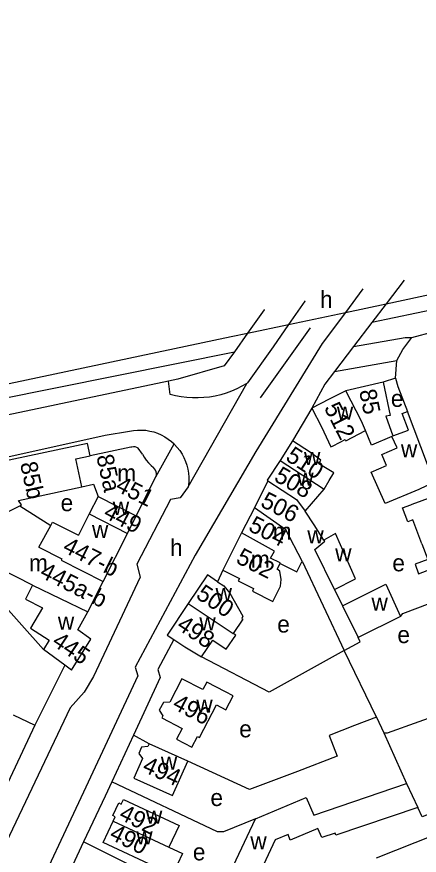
# Model space of a CAD drawing. Extents: x 163026 to 166241, y 382475 to 384501.
# Drawn here: x 163806.9 to 163901.8, y 384015.1 to 384213 of the extents above; entities that cross this region are included whole.
import ezdxf

# ---------------------------------------------------------------- set-up
doc = ezdxf.new("R2010")
doc.units = 0
for name, color, linetype in [('BLT_Basislijn', 7, 'Continuous'), ('BLT_Bebouwing', 7, 'Continuous'), ('BLT_Centroide', 7, 'Continuous'), ('BLT_Huisnummer', 7, 'Continuous'), ('BLT_Huisnummer_ tussenligend', 7, 'Continuous'), ('BLT_Huisnummer_reeks', 7, 'Continuous'), ('BLT_Onderverdeling_panden', 7, 'Continuous'), ('BLT_Spoorlijn', 7, 'Continuous'), ('BLT_Vlakafsluiter', 7, 'Continuous')]:
    doc.layers.add(name, color=color, linetype=linetype)

msp = doc.modelspace()

# ---------------------------------------------------------------- linework, layer by layer
at = {"layer": 'BLT_Basislijn'}
for p, q in [((163969.43, 384157.19), (163890.65, 384140.81)), ((163898.25, 384150.79), (163894.03, 384145.25)), ((163865.29, 384143.83), (163861.35, 384138.3)), ((163894.03, 384145.25), (163890.65, 384140.81)), ((163876.12, 384139.55), (163864.3, 384123.02)), ((163890.65, 384140.81), (163886.32, 384135.12)), ((163861.35, 384138.3), (163858.24, 384133.92)), ((163787.39, 384119.63), (163858.24, 384133.92)), ((163858.24, 384133.92), (163855.85, 384130.55)), ((163886.32, 384135.12), (163881.85, 384129.25)), ((163881.85, 384129.25), (163896.54, 384131.86)), ((163896.24, 384127.64), (163896.54, 384131.86)), ((163855.85, 384130.55), (163844.94, 384127.47)), ((163896.24, 384127.64), (163893.35, 384126.7)), ((163844.94, 384127.47), (163842.68, 384126.99)), ((163843.09, 384123.84), (163842.68, 384126.99)), ((163876.52, 384120.62), (163871.98, 384112.85)), ((163839.75, 384104.35), (163844.03, 384112.15)), ((163813.27, 384063.63), (163795.65, 384083.33)), ((163855.5, 384082.37), (163854.28, 384079.63)), ((163891.8, 384047.64), (163884.13, 384063.39)), ((163818.29, 384059.92), (163811.17, 384045.74)), ((163806.07, 384048.22), (163811.17, 384045.74)), ((163891.8, 384047.64), (163893.52, 384043.92)), ((163811.17, 384045.74), (163788.45, 383997.79)), ((163834.43, 384043.38), (163829.33, 384032.4)), ((163838.14, 384041.35), (163834.43, 384043.38)), ((163893.52, 384043.92), (163898.8, 384032.01)), ((163822.68, 384018.2), (163814.06, 383999.82)), ((163853.46, 384002.93), (163822.68, 384018.2))]:
    msp.add_line(p, q, dxfattribs=at)
for points in [[(163900.11, 384137.3), (163905.37, 384138.71), (164182.17, 384196.48), (164249.9, 384212.98), (164253.88, 384212.82), (164257.32, 384211.62), (164261.05, 384208.36), (164262.81, 384205.4), (164265.99, 384192.34), (164268.94, 384175.29), (164269.89, 384164.18), (164270.1, 384149.11), (164272.14, 384146.86), (164275.23, 384146.44), (164277.11, 384147)], [(163888.54, 384148.75), (163884.42, 384143.2)], [(163874.87, 384145.84), (163871.05, 384140.36)], [(163874.92, 384145.9), (163874.87, 384145.84)], [(163865.33, 384143.89), (163865.29, 384143.83)], [(163884.42, 384143.2), (163878.98, 384135.87), (163863.28, 384110.37), (163849.01, 384085.89)], [(163871.05, 384140.36), (163867.36, 384135.06), (163861.31, 384126.59)], [(163886.32, 384135.12), (163898.52, 384137.28), (163900.11, 384137.3)], [(163896.54, 384131.86), (163898, 384134.42), (163900.11, 384137.3)], [(163881.85, 384129.25), (163879.59, 384126.29), (163876.52, 384120.62)], [(163896.24, 384127.64), (163896.81, 384125.69), (163899.1, 384119.78)], [(163842.68, 384126.99), (163680.68, 384092.81), (163440.33, 384043.29)], [(163861.15, 384126.44), (163860, 384125.76), (163858.8, 384125.15), (163857.57, 384124.61), (163856.31, 384124.15), (163855.03, 384123.76), (163853.72, 384123.46), (163852.4, 384123.22), (163851.07, 384123.07), (163849.73, 384123), (163848.38, 384123.01), (163847.04, 384123.1), (163845.71, 384123.27), (163844.39, 384123.51), (163843.09, 384123.84)], [(163861.31, 384126.59), (163861.25, 384126.51), (163861.15, 384126.44)], [(163779.97, 384103.61), (163827.81, 384114.22), (163833.51, 384115.18)], [(163833.51, 384115.18), (163834.46, 384115.35), (163835.42, 384115.43), (163836.38, 384115.43), (163837.34, 384115.36), (163838.29, 384115.2), (163839.22, 384114.97), (163840.13, 384114.66), (163841.02, 384114.27), (163841.86, 384113.82), (163842.67, 384113.29), (163843.43, 384112.7), (163844.03, 384112.15)], [(163844.03, 384112.15), (163844.14, 384112.05), (163844.79, 384111.34), (163845.38, 384110.58), (163845.9, 384109.77), (163846.36, 384108.92), (163846.74, 384108.04), (163847.05, 384107.13), (163847.29, 384106.2), (163847.44, 384105.25), (163847.52, 384104.29), (163847.51, 384103.33), (163847.43, 384102.37), (163847.37, 384102.01)], [(163847.37, 384102.01), (163845.44, 384099.45), (163843.19, 384099.05), (163835.24, 384083.74), (163836.06, 384080.68), (163825.05, 384057.22), (163822.81, 384053.55), (163819.54, 384049.88), (163804.46, 384018.05)], [(163849.01, 384085.89), (163834.84, 384059.46), (163835.45, 384057.42), (163823.21, 384031.1), (163809.15, 384001.11), (163805.88, 383997.85)], [(163897.43, 384071.44), (163897.96, 384072.12), (163904.4, 384074.58)], [(163844, 384065.97), (163840.22, 384058.92), (163840.78, 384057.04), (163834.43, 384043.38)], [(163884.13, 384063.39), (163866.49, 384053.56), (163850.51, 384061.87)], [(163923.18, 384054.38), (163930.98, 384035.41), (163902.51, 384024.13), (163901.48, 384026.31)], [(163893.52, 384043.92), (163894.32, 384043.98), (163909.33, 384049.29)], [(163891.8, 384047.64), (163886.54, 384045.65), (163880.62, 384043.34), (163882.46, 384038.46), (163873.12, 384034.83), (163861.81, 384030.6), (163847.31, 384037.23)], [(163829.33, 384032.4), (163827.74, 384028.99), (163822.68, 384018.2)], [(163863.25, 384023.62), (163855.66, 384020.56), (163854.29, 384020.61), (163829.33, 384032.4)], [(163891.79, 384014.44), (163932, 384030.42), (163939.47, 384011.72), (163939.8, 384010.54)]]:
    msp.add_lwpolyline(points, dxfattribs=at)
at = {"layer": 'BLT_Bebouwing'}
for p, q in [((163905.38, 384103.11), (163899.1, 384119.78)), ((163871.98, 384112.85), (163869.01, 384108.25)), ((163833.86, 384111.36), (163824.22, 384109.32)), ((163836.6, 384109.72), (163835.58, 384111.14)), ((163835.11, 384095.14), (163839.75, 384104.35)), ((163807.31, 384098.8), (163822.3, 384102.05)), ((163822.3, 384102.05), (163825.01, 384102.63)), ((163825.01, 384102.63), (163826.1, 384099.71)), ((163866.15, 384103.4), (163862.96, 384097.1)), ((163874.91, 384096.29), (163879.44, 384101.5)), ((163826.1, 384099.71), (163824.04, 384095.66)), ((163807.68, 384097.56), (163814.93, 384092.93)), ((163862.96, 384097.1), (163859.96, 384091.18)), ((163824.04, 384095.66), (163821.48, 384090.61)), ((163833.04, 384091.04), (163835.11, 384095.14)), ((163827.3, 384079.68), (163833.04, 384091.04)), ((163859.96, 384091.18), (163855.5, 384082.37)), ((163823.68, 384072.51), (163827.3, 384079.68)), ((163881.85, 384077.8), (163883.76, 384073.93)), ((163819.84, 384058.77), (163824.4, 384066.03)), ((163844, 384065.97), (163846.6, 384064.24)), ((163846.6, 384064.24), (163850.51, 384061.87)), ((163818.29, 384059.92), (163813.27, 384063.63)), ((163819.84, 384058.77), (163818.29, 384059.92)), ((163898.8, 384032.01), (163901.48, 384026.31))]:
    msp.add_line(p, q, dxfattribs=at)
for points in [[(163893.35, 384126.7), (163884.52, 384124.72)], [(163893.35, 384126.7), (163894.97, 384118.89), (163893.97, 384118.68), (163895.6, 384114.04)], [(163884.52, 384124.72), (163880.64, 384122.73), (163876.52, 384120.62)], [(163876.52, 384120.62), (163878.78, 384116.17), (163880.99, 384111.5), (163881.42, 384111.59), (163883.16, 384112.53), (163884.34, 384113.17), (163884.5, 384112.88), (163889.15, 384115.32)], [(163895.6, 384114.04), (163899.3, 384115.43), (163897.84, 384119.3), (163899.1, 384119.78)], [(163895.4, 384113.89), (163890.59, 384111.87), (163889.15, 384115.32)], [(163905.38, 384103.11), (163901.76, 384101.43), (163893.77, 384098.05), (163890.52, 384105.5), (163894.14, 384107.07), (163893.02, 384109.64), (163896.61, 384111.21), (163895.4, 384113.89)], [(163824.22, 384109.32), (163823.61, 384112.25), (163795.05, 384106.22), (163796.06, 384103.37)], [(163879.44, 384101.5), (163880.64, 384103.49), (163881.74, 384105.32), (163878.13, 384107.48), (163878.65, 384108.34), (163876.17, 384110.13), (163871.98, 384112.85)], [(163835.58, 384111.14), (163835.23, 384111.32), (163834.84, 384111.43), (163834.45, 384111.46), (163834.06, 384111.41), (163833.86, 384111.36)], [(163836.6, 384109.72), (163837, 384108.99), (163837.46, 384108.31), (163838, 384107.67), (163838.59, 384107.08), (163839.16, 384106.61)], [(163869.01, 384108.25), (163866.01, 384103.62), (163866.15, 384103.4)], [(163839.75, 384104.35), (163839.85, 384104.75), (163839.86, 384105.16), (163839.8, 384105.57), (163839.66, 384105.95), (163839.44, 384106.3), (163839.17, 384106.61), (163839.16, 384106.61)], [(163807.68, 384097.56), (163808.03, 384097.74), (163807.31, 384098.8)], [(163902.48, 384088.55), (163900.33, 384094.23), (163899.15, 384093.78), (163897.91, 384097.05), (163899.83, 384097.77), (163900.2, 384097.91), (163904.87, 384099.68), (163906.07, 384096.52), (163907.07, 384096.9)], [(163879.38, 384089.45), (163877.03, 384093.05), (163874.91, 384096.29)], [(163810.65, 384078.82), (163798.71, 384084.88), (163804.89, 384089.78), (163802.84, 384092.04)], [(163814.93, 384092.93), (163815.35, 384093.72), (163821.48, 384090.61)], [(163881.85, 384077.8), (163886.84, 384080.3), (163882.11, 384091), (163879.38, 384089.45)], [(163902.48, 384088.55), (163903.87, 384084.89), (163900.85, 384083.74), (163901.7, 384081.5), (163904.7, 384082.69)], [(163869.01, 384083.94), (163872.96, 384081.94), (163874.24, 384084.47)], [(163874.24, 384084.47), (163884.13, 384063.39)], [(163855.5, 384082.37), (163859.42, 384080.39), (163859.14, 384079.83), (163862.78, 384077.99), (163862.49, 384077.41), (163867.33, 384074.96), (163869.15, 384078.57), (163869.27, 384080.16), (163868.93, 384082.14), (163868.33, 384082.61), (163869.01, 384083.94)], [(163854.28, 384079.63), (163851.89, 384081.23), (163847.37, 384074.46)], [(163810.65, 384078.82), (163808.96, 384075.49), (163813, 384073.44), (163810.2, 384068.68), (163814.61, 384065.86), (163813.27, 384063.63)], [(163854.28, 384079.63), (163855.76, 384078.65), (163857.16, 384076.94), (163860.25, 384071.47), (163860, 384070.97), (163860.24, 384070.8), (163857.97, 384067.4)], [(163883.76, 384073.93), (163893.99, 384079.07), (163897.43, 384071.44)], [(163847.37, 384074.46), (163842.41, 384067.03), (163844, 384065.97)], [(163824.4, 384066.03), (163821.36, 384068.23), (163823.68, 384072.51)], [(163897.43, 384071.44), (163887.44, 384066.49)], [(163850.51, 384061.87), (163853.15, 384065.82), (163856.31, 384063.71), (163858.62, 384066.97), (163857.97, 384067.4)], [(163884.13, 384063.39), (163887.95, 384065.46), (163887.44, 384066.49)], [(163856.26, 384049.42), (163857.97, 384052.69), (163856.18, 384053.63), (163851.74, 384055.95), (163850.81, 384054.15), (163845.89, 384056.72), (163843.01, 384051.2), (163841.52, 384051.14), (163840.55, 384049.28), (163841.39, 384047.97), (163841.15, 384047.52), (163845.94, 384045.01), (163844.6, 384042.46), (163848.24, 384040.56), (163849.57, 384043.1), (163850.02, 384042.87), (163854.04, 384050.57), (163856.26, 384049.42)], [(163838.14, 384041.35), (163837.85, 384040.69), (163836.35, 384040.54), (163835.71, 384039.11), (163836.6, 384037.88), (163834.52, 384033.26), (163839.08, 384031.21), (163843.67, 384029.14), (163847.31, 384037.23)], [(163847.31, 384037.23), (163842.71, 384039.3), (163838.14, 384041.35)], [(163875.21, 384028.67), (163876.97, 384024.51), (163898.8, 384032.01)], [(163863.25, 384023.62), (163875.21, 384028.67)], [(163829.69, 384023.13), (163830.14, 384024.14), (163829.58, 384024.41), (163830.97, 384027.42), (163831.56, 384027.14), (163832.07, 384028.23), (163845.2, 384022.08), (163842.83, 384016.99)], [(163901.48, 384026.31), (163882.18, 384019.8), (163881.99, 384020.3), (163878.85, 384019.21), (163877.95, 384021.4), (163871.44, 384018.65), (163870.9, 384019.94), (163867.9, 384018.68), (163862.99, 384008.21), (163862.34, 384005.84), (163863.43, 384003.15)], [(163842.83, 384016.99), (163846.03, 384015.49), (163843.65, 384010.4), (163840.45, 384011.9), (163827.33, 384018.08), (163829.69, 384023.13)], [(163853.46, 384002.93), (163863.25, 384023.62)]]:
    msp.add_lwpolyline(points, dxfattribs=at)
at = {"layer": 'BLT_Onderverdeling_panden'}
for p, q in [((163869.01, 384108.25), (163879.44, 384101.5)), ((163826.1, 384099.71), (163835.11, 384095.14)), ((163800.93, 384094.15), (163807.68, 384097.56)), ((163824.04, 384095.66), (163833.04, 384091.04)), ((163812.15, 384087.75), (163814.93, 384092.93)), ((163810.65, 384078.82), (163823.68, 384072.51)), ((163847.37, 384074.46), (163857.97, 384067.4)), ((163883.76, 384073.93), (163887.44, 384066.49)), ((163829.69, 384023.13), (163842.83, 384016.99))]:
    msp.add_line(p, q, dxfattribs=at)
for points in [[(163889.15, 384115.32), (163888.22, 384117.56), (163884.52, 384124.72)], [(163822.3, 384102.05), (163820.88, 384108.62), (163824.22, 384109.32)], [(163866.15, 384103.4), (163872.91, 384099.02), (163874.91, 384096.29)], [(163874.24, 384084.47), (163870.37, 384091.9), (163862.96, 384097.1)], [(163869.01, 384083.94), (163869.06, 384084.08), (163866.8, 384085.22), (163867.72, 384086.87), (163859.96, 384091.18)], [(163881.85, 384077.8), (163877.2, 384087.2), (163879.56, 384089.16), (163879.38, 384089.45)], [(163812.15, 384087.75), (163817.55, 384084.99), (163817.43, 384084.75), (163827.3, 384079.68)]]:
    msp.add_lwpolyline(points, dxfattribs=at)
at = {"layer": 'BLT_Spoorlijn'}
for points in [[(163894.03, 384145.25), (163917.02, 384150.14), (163980.39, 384163.11)], [(163884.42, 384143.2), (163894.03, 384145.25)], [(163871.05, 384140.36), (163884.42, 384143.2)], [(163861.35, 384138.3), (163871.05, 384140.36)], [(163787.6, 384122.75), (163857.5, 384137.48), (163861.35, 384138.3)]]:
    msp.add_lwpolyline(points, dxfattribs=at)
at = {"layer": 'BLT_Vlakafsluiter'}
msp.add_line((163847.37, 384102.01), (163861.15, 384126.44), dxfattribs=at)

# ---------------------------------------------------------------- texts
at = {"layer": 'BLT_Centroide'}
for s, p in [('h', (163878.44, 384144.26)), ('e', (163895.15, 384120.89)), ('w', (163882.41, 384117.89)), ('w', (163897.52, 384108.99)), ('w', (163874.67, 384107.19)), ('m', (163830.62, 384103.31)), ('w', (163873.07, 384102.28)), ('e', (163817.27, 384096.27)), ('w', (163829.57, 384095.41)), ('w', (163824.66, 384089.97)), ('m', (163867.28, 384089.53)), ('w', (163875.45, 384088.67)), ('h', (163843.06, 384085.68)), ('m', (163862.14, 384082.94)), ('w', (163882.02, 384084.41)), ('m', (163809.81, 384082.07)), ('e', (163895.5, 384082.08)), ('w', (163853.81, 384075.05)), ('w', (163890.58, 384072.78)), ('w', (163816.62, 384068.3)), ('w', (163849.99, 384068.16)), ('e', (163868.36, 384067.62)), ('e', (163896.69, 384065.14)), ('w', (163849.27, 384048.73)), ('e', (163859.39, 384042.89)), ('w', (163840.91, 384035.25)), ('e', (163852.6, 384026.68)), ('w', (163837.39, 384022.53)), ('w', (163835.11, 384017.62)), ('w', (163862.01, 384016.44)), ('e', (163848.46, 384013.85))]:
    msp.add_text(s, height=4, dxfattribs=at).set_placement(p)
at = {"layer": 'BLT_Huisnummer'}
for s, rotation, p in [('85', 281.7106, (163887.65, 384124.67)), ('512', 297.0519, (163879.3, 384120.7)), ('510', 327.1007, (163870.09, 384108.45)), ('85b', 282.2508, (163807.68, 384107.53)), ('506', 333.136, (163864.16, 384097.49)), ('449', 333.1021, (163827.11, 384094.9)), ('447-b', 333.2263, (163817.49, 384086.82)), ('502', 333.1324, (163858.37, 384084.21)), ('500', 326.3074, (163848.94, 384075.92)), ('498', 326.3036, (163844.39, 384068.65)), ('445', 326.116, (163814.99, 384064.81)), ('496', 332.417, (163843.4, 384049.82)), ('494', 335.752, (163836.31, 384034.94)), ('492', 333.6154, (163830.78, 384023.72)), ('490', 333.6154, (163828.54, 384019.03))]:
    msp.add_text(s, height=4, rotation=rotation, dxfattribs=at).set_placement(p)
at = {"layer": 'BLT_Huisnummer_ tussenligend'}
for s, rotation, p in [('508', 330.136, (163867.35, 384103.58)), ('504', 333.1324, (163861.3, 384091.79))]:
    msp.add_text(s, height=4, rotation=rotation, dxfattribs=at).set_placement(p)
at = {"layer": 'BLT_Huisnummer_reeks'}
for s, rotation, p in [('85a', 282.2162, (163825.68, 384109.25)), ('451', 333.1003, (163829.97, 384101.22)), ('445a-b', 333.1013, (163812.1, 384080.88))]:
    msp.add_text(s, height=4, rotation=rotation, dxfattribs=at).set_placement(p)

doc.saveas('drawing.dxf')
